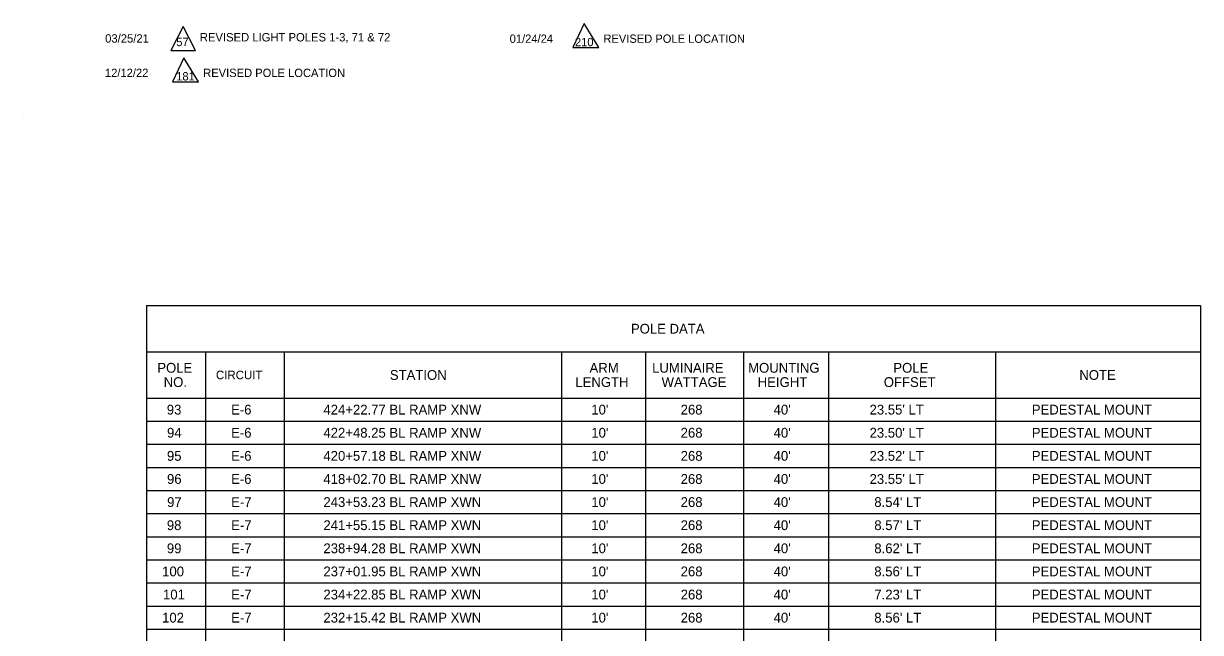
# Model space of a CAD drawing. Extents: x -818.1 to -802.4, y -2221.2 to -2187.7.
# Drawn here: x -818.09 to -809.69, y -2201.81 to -2197.46 of the extents above; entities that cross this region are included whole.
import ezdxf

# ---------------------------------------------------------------- set-up
doc = ezdxf.new("R2010")
doc.units = 0
for name, color, linetype in [('PlotBorder_dp', 7, 'Continuous'), ('SheetBorder_dp', 7, 'Continuous'), ('SheetLines_dp', 7, 'Continuous'), ('TextMinor', 7, 'Continuous'), ('TextShtNo', 7, 'Continuous'), ('TextTitle', 7, 'Continuous')]:
    doc.layers.add(name, color=color, linetype=linetype)

msp = doc.modelspace()

# ---------------------------------------------------------------- linework, layer by layer
at = {"layer": 'PlotBorder_dp'}
for p, q in [((-816.7882, -2199.8042), (-816.7882, -2206.2692)), ((-816.7882, -2199.8042), (-816.7882, -2206.2692)), ((-816.2257, -2199.8042), (-816.2257, -2206.2692)), ((-816.2257, -2199.8042), (-816.2257, -2206.2692)), ((-814.2457, -2199.8042), (-814.2457, -2206.2692)), ((-814.2457, -2199.8042), (-814.2457, -2206.2692)), ((-813.6457, -2199.8042), (-813.6457, -2206.2692)), ((-813.6457, -2199.8042), (-813.6457, -2206.2692)), ((-812.9482, -2199.8042), (-812.9482, -2206.2692)), ((-812.9482, -2199.8042), (-812.9482, -2206.2692)), ((-812.3407, -2199.8042), (-812.3407, -2206.2692)), ((-812.3407, -2199.8042), (-812.3407, -2206.2692)), ((-811.1482, -2199.8042), (-811.1482, -2206.2692)), ((-811.1482, -2199.8042), (-811.1482, -2206.2692)), ((-817.2082, -2200.1342), (-809.6857, -2200.1342))]:
    msp.add_line(p, q, dxfattribs=at)
at = {"layer": 'SheetLines_dp'}
for p, q in [((-817.2082, -2199.4742), (-809.6857, -2199.4742)), ((-817.2082, -2199.4742), (-817.2082, -2206.2692)), ((-809.6857, -2199.4742), (-809.6857, -2206.2692)), ((-817.2082, -2199.8042), (-809.6857, -2199.8042)), ((-817.2082, -2199.8042), (-809.6857, -2199.8042))]:
    msp.add_line(p, q, dxfattribs=at)
at = {"layer": 'TextMinor'}
for p, q in [((-817.2082, -2200.1342), (-809.6857, -2200.1342)), ((-817.2082, -2200.2992), (-809.6857, -2200.2992)), ((-817.2082, -2200.2992), (-809.6857, -2200.2992)), ((-817.2082, -2200.4642), (-809.6857, -2200.4642)), ((-817.2082, -2200.4642), (-809.6857, -2200.4642)), ((-817.2082, -2200.6292), (-809.6857, -2200.6292)), ((-817.2082, -2200.6292), (-809.6857, -2200.6292)), ((-817.2082, -2200.7942), (-809.6857, -2200.7942)), ((-817.2082, -2200.7942), (-809.6857, -2200.7942)), ((-817.2082, -2200.9592), (-809.6857, -2200.9592)), ((-817.2082, -2200.9592), (-809.6857, -2200.9592)), ((-817.2082, -2201.1242), (-809.6857, -2201.1242)), ((-817.2082, -2201.1242), (-809.6857, -2201.1242)), ((-817.2082, -2201.2892), (-809.6857, -2201.2892)), ((-817.2082, -2201.2892), (-809.6857, -2201.2892)), ((-817.2082, -2201.4542), (-809.6857, -2201.4542)), ((-817.2082, -2201.4542), (-809.6857, -2201.4542)), ((-817.2082, -2201.6192), (-809.6857, -2201.6192)), ((-817.2082, -2201.6192), (-809.6857, -2201.6192)), ((-817.2082, -2201.7842), (-809.6857, -2201.7842)), ((-817.2082, -2201.7842), (-809.6857, -2201.7842))]:
    msp.add_line(p, q, dxfattribs=at)
at = {"layer": 'TextShtNo'}
msp.add_line((-818.0862, -2198.1071), (-818.0862, -2198.1071), dxfattribs=at)
at = {"layer": 'TextTitle'}
for points in [[(-816.946, -2197.4826), (-817.034, -2197.6522), (-816.8579, -2197.6522)], [(-814.0844, -2197.4606), (-814.1652, -2197.6318), (-813.9808, -2197.6318)], [(-816.9415, -2197.7044), (-817.0225, -2197.876), (-816.8377, -2197.876)]]:
    msp.add_lwpolyline(points, close=True, dxfattribs=at)

# ---------------------------------------------------------------- texts
at = {"layer": 'SheetBorder_dp'}
for s, height, p in [('POLE DATA', 0.07, (-813.7508, -2199.6742)), ('POLE', 0.07, (-817.1315, -2199.9532)), ('ARM', 0.07, (-814.0462, -2199.9532)), ('LUMINAIRE', 0.07, (-813.5996, -2199.9532)), ('MOUNTING', 0.07, (-812.9141, -2199.9532)), ('POLE', 0.07, (-811.8777, -2199.9532)), ('NO.', 0.07, (-817.0858, -2200.0552)), ('CIRCUIT', 0.06125, (-816.7129, -2199.9998)), ('STATION', 0.07, (-815.4715, -2200.0042)), ('LENGTH', 0.07, (-814.1476, -2200.0552)), ('WATTAGE', 0.07, (-813.5318, -2200.0552)), ('HEIGHT', 0.07, (-812.8459, -2200.0552)), ('OFFSET', 0.07, (-811.9459, -2200.0552)), ('NOTE', 0.07, (-810.5502, -2200.0042)), ('93', 0.07, (-817.0635, -2200.2517)), ('E-6', 0.07, (-816.6047, -2200.2517)), ('424+22.77 BL RAMP XNW', 0.07, (-815.9458, -2200.2517)), ("10'", 0.07, (-814.0336, -2200.2517)), ('268', 0.07, (-813.3958, -2200.2517)), ("40'", 0.07, (-812.7324, -2200.2517)), ("23.55' LT", 0.07, (-812.0475, -2200.2517)), ('PEDESTAL MOUNT', 0.07, (-810.8894, -2200.2517)), ('94', 0.07, (-817.0621, -2200.4167)), ('E-6', 0.07, (-816.6047, -2200.4167)), ('422+48.25 BL RAMP XNW', 0.07, (-815.9458, -2200.4167)), ("10'", 0.07, (-814.0336, -2200.4167)), ('268', 0.07, (-813.3958, -2200.4167)), ("40'", 0.07, (-812.7324, -2200.4167)), ("23.50' LT", 0.07, (-812.0475, -2200.4167)), ('PEDESTAL MOUNT', 0.07, (-810.8894, -2200.4167)), ('95', 0.07, (-817.0626, -2200.5817)), ('E-6', 0.07, (-816.6047, -2200.5817)), ('420+57.18 BL RAMP XNW', 0.07, (-815.9458, -2200.5817)), ("10'", 0.07, (-814.0336, -2200.5817)), ('268', 0.07, (-813.3958, -2200.5817)), ("40'", 0.07, (-812.7324, -2200.5817)), ("23.52' LT", 0.07, (-812.0475, -2200.5817)), ('PEDESTAL MOUNT', 0.07, (-810.8894, -2200.5817)), ('96', 0.07, (-817.0621, -2200.7467)), ('E-6', 0.07, (-816.6047, -2200.7467)), ('418+02.70 BL RAMP XNW', 0.07, (-815.9458, -2200.7467)), ("10'", 0.07, (-814.0336, -2200.7467)), ('268', 0.07, (-813.3958, -2200.7467)), ("40'", 0.07, (-812.7324, -2200.7467)), ("23.55' LT", 0.07, (-812.0475, -2200.7467)), ('PEDESTAL MOUNT', 0.07, (-810.8894, -2200.7467)), ('97', 0.07, (-817.0615, -2200.9117)), ('E-7', 0.07, (-816.6041, -2200.9117)), ('243+53.23 BL RAMP XWN', 0.07, (-815.9458, -2200.9117)), ("10'", 0.07, (-814.0336, -2200.9117)), ('268', 0.07, (-813.3958, -2200.9117)), ("40'", 0.07, (-812.7324, -2200.9117)), ("8.54' LT", 0.07, (-812.0137, -2200.9117)), ('PEDESTAL MOUNT', 0.07, (-810.8894, -2200.9117)), ('98', 0.07, (-817.0632, -2201.0767)), ('E-7', 0.07, (-816.6041, -2201.0767)), ('241+55.15 BL RAMP XWN', 0.07, (-815.9458, -2201.0767)), ("10'", 0.07, (-814.0336, -2201.0767)), ('268', 0.07, (-813.3958, -2201.0767)), ("40'", 0.07, (-812.7324, -2201.0767)), ("8.57' LT", 0.07, (-812.0137, -2201.0767)), ('PEDESTAL MOUNT', 0.07, (-810.8894, -2201.0767)), ('99', 0.07, (-817.0631, -2201.2417)), ('E-7', 0.07, (-816.6041, -2201.2417)), ('238+94.28 BL RAMP XWN', 0.07, (-815.9458, -2201.2417)), ("10'", 0.07, (-814.0336, -2201.2417)), ('268', 0.07, (-813.3958, -2201.2417)), ("40'", 0.07, (-812.7324, -2201.2417)), ("8.62' LT", 0.07, (-812.0137, -2201.2417)), ('PEDESTAL MOUNT', 0.07, (-810.8894, -2201.2417)), ('100', 0.07, (-817.0968, -2201.4067)), ('E-7', 0.07, (-816.6041, -2201.4067)), ('237+01.95 BL RAMP XWN', 0.07, (-815.9458, -2201.4067)), ("10'", 0.07, (-814.0336, -2201.4067)), ('268', 0.07, (-813.3958, -2201.4067)), ("40'", 0.07, (-812.7324, -2201.4067)), ("8.56' LT", 0.07, (-812.0137, -2201.4067)), ('PEDESTAL MOUNT', 0.07, (-810.8894, -2201.4067)), ('101', 0.07, (-817.0906, -2201.5717)), ('E-7', 0.07, (-816.6041, -2201.5717)), ('234+22.85 BL RAMP XWN', 0.07, (-815.9458, -2201.5717)), ("10'", 0.07, (-814.0336, -2201.5717)), ('268', 0.07, (-813.3958, -2201.5717)), ("40'", 0.07, (-812.7324, -2201.5717)), ("7.23' LT", 0.07, (-812.0137, -2201.5717)), ('PEDESTAL MOUNT', 0.07, (-810.8894, -2201.5717)), ('102', 0.07, (-817.0973, -2201.7367)), ('E-7', 0.07, (-816.6041, -2201.7367)), ('232+15.42 BL RAMP XWN', 0.07, (-815.9458, -2201.7367)), ("10'", 0.07, (-814.0336, -2201.7367)), ('268', 0.07, (-813.3958, -2201.7367)), ("40'", 0.07, (-812.7324, -2201.7367)), ("8.56' LT", 0.07, (-812.0137, -2201.7367)), ('PEDESTAL MOUNT', 0.07, (-810.8894, -2201.7367))]:
    msp.add_text(s, height=height, dxfattribs=at).set_placement(p)
at = {"layer": 'TextTitle'}
for s, height, p in [('03/25/21', 0.06, (-817.5037, -2197.597)), ('57', 0.06, (-816.9966, -2197.622)), ('REVISED LIGHT POLES 1-3, 71 & 72', 0.06, (-816.8278, -2197.5884)), ('01/24/24', 0.05938, (-814.6162, -2197.5983)), ('210', 0.05938, (-814.1502, -2197.6226)), ('REVISED POLE LOCATION', 0.059382, (-813.9472, -2197.5983)), ('12/12/22', 0.05952, (-817.505, -2197.8424)), ('181', 0.05952, (-816.9966, -2197.8669)), ('REVISED POLE LOCATION', 0.05952, (-816.804, -2197.8424))]:
    msp.add_text(s, height=height, dxfattribs=at).set_placement(p)

doc.saveas('drawing.dxf')
